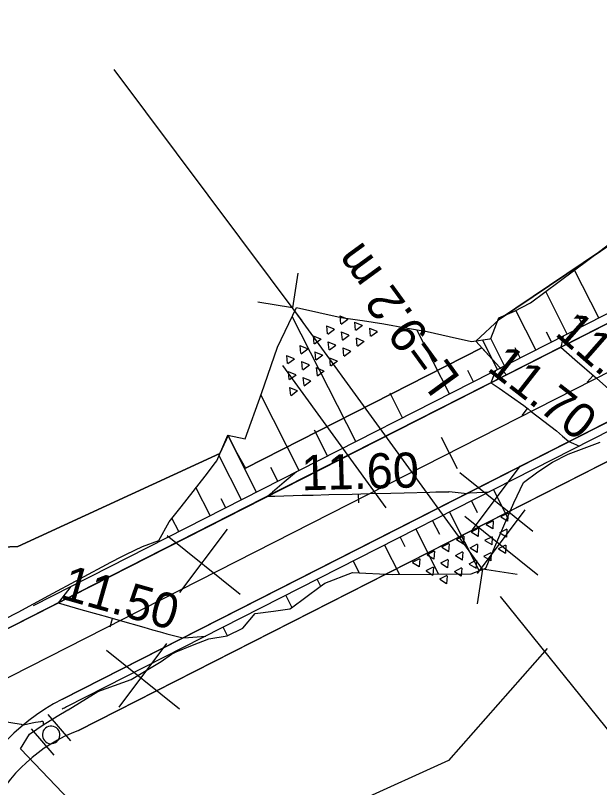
# Model space of a CAD drawing. Extents: x 554247.5 to 554326.1, y 6593477.6 to 6593537.1.
# Drawn here: x 554264.74 to 554281.38, y 6593498.07 to 6593520.04 of the extents above; entities that cross this region are included whole.
import ezdxf

# ---------------------------------------------------------------- set-up
doc = ezdxf.new("R2010")
doc.units = 0
for name, color, linetype in [('ASF', 7, 'Continuous'), ('FILL ASF KT', 7, 'Continuous'), ('FILL ROHELINE', 7, 'Continuous'), ('HATCH SILLUTIS', 7, 'Continuous'), ('KRAAV PUHASTAMINE', 7, 'Continuous'), ('LIIKLUSMÄRK', 7, 'Continuous'), ('LIKV', 7, 'Continuous'), ('NÕLV', 7, 'Continuous'), ('PIIRE TÕKKEPUU', 7, 'Continuous'), ('PK', 7, 'Continuous'), ('TELG', 7, 'Continuous'), ('TRUUP', 7, 'Continuous'), ('TRUUP TXT', 7, 'Continuous'), ('VERT', 7, 'Continuous')]:
    doc.layers.add(name, color=color, linetype=linetype)

msp = doc.modelspace()

# ---------------------------------------------------------------- linework, layer by layer
at = {"layer": 'ASF'}
for points in [[(554264.161, 6593502.412), (554285.444, 6593513.231)], [(554286.577, 6593511.002), (554266.083, 6593500.584)]]:
    msp.add_lwpolyline(points, dxfattribs=at)
msp.add_arc((554268.802, 6593495.236), 6, 116.9456, 201.6745, dxfattribs=at)
at = {"layer": 'FILL ASF KT'}
for p, q in [((554285.444, 6593513.231), (554264.161, 6593502.412)), ((554266.083, 6593500.584), (554286.577, 6593511.002))]:
    msp.add_line(p, q, dxfattribs=at)
msp.add_arc((554268.802, 6593495.236), 6, 116.9456, 201.6745, dxfattribs=at)
at = {"layer": 'FILL ROHELINE'}
for p, q in [((554286.577, 6593511.002), (554266.083, 6593500.584)), ((554266.536, 6593499.693), (554287.03, 6593510.111)), ((554264.161, 6593502.412), (554271.79, 6593506.29))]:
    msp.add_line(p, q, dxfattribs=at)
for points in [[(554277.854, 6593510.768), (554278.526, 6593511.403), (554281.872, 6593513.649), (554285.905, 6593516.209), (554288.219, 6593518.918), (554288.941, 6593519.616), (554289.857, 6593520.042), (554293.053, 6593519.84), (554293.641, 6593519.03), (554290.413, 6593516.439)], [(554290.413, 6593516.439), (554293.641, 6593519.03), (554293.053, 6593519.84), (554289.857, 6593520.042), (554288.941, 6593519.616), (554288.219, 6593518.918), (554285.905, 6593516.209), (554281.872, 6593513.649), (554278.526, 6593511.403), (554277.854, 6593510.768)], [(554285.444, 6593513.231), (554278.724, 6593509.815), (554277.854, 6593510.768)], [(554277.854, 6593510.768), (554278.724, 6593509.815), (554285.444, 6593513.231)], [(554266.083, 6593500.584), (554286.577, 6593511.002)], [(554257.556, 6593501.544), (554257.446, 6593501.567), (554257.204, 6593502.641), (554256.756, 6593504.598), (554264.814, 6593504.931), (554270.559, 6593507.573), (554270.797, 6593508.088), (554271.046, 6593507.591), (554271.293, 6593507.159), (554278.029, 6593510.583), (554278.724, 6593509.815), (554271.79, 6593506.29)], [(554271.79, 6593506.29), (554278.724, 6593509.815), (554278.029, 6593510.583), (554271.293, 6593507.159), (554271.046, 6593507.591), (554270.797, 6593508.088), (554270.559, 6593507.573), (554264.814, 6593504.931), (554256.756, 6593504.598), (554257.204, 6593502.641), (554257.446, 6593501.567), (554257.556, 6593501.544)], [(554287.03, 6593510.111), (554266.536, 6593499.693)], [(554271.79, 6593506.29), (554264.161, 6593502.412)]]:
    msp.add_lwpolyline(points, dxfattribs=at)
for centre, radius, start, end in [((554268.802, 6593495.236), 6, 116.9456, 201.6745), ((554268.802, 6593495.236), 6, 116.9456, 201.6745), ((554268.171, 6593495.373), 4.619, 110.7356, 154.1385), ((554268.171, 6593495.373), 4.619, 110.7356, 154.1385)]:
    msp.add_arc(centre, radius, start, end, dxfattribs=at)
at = {"layer": 'HATCH SILLUTIS'}
for p, q in [((554274.197, 6593511.394), (554273.986, 6593511.481)), ((554274.009, 6593511.262), (554273.987, 6593511.49)), ((554274.016, 6593511.258), (554274.206, 6593511.398)), ((554274.431, 6593511.089), (554274.409, 6593511.317)), ((554274.62, 6593511.221), (554274.409, 6593511.307)), ((554273.63, 6593510.981), (554273.608, 6593511.208)), ((554273.819, 6593511.113), (554273.608, 6593511.199)), ((554273.638, 6593510.976), (554273.827, 6593511.117)), ((554274.439, 6593511.084), (554274.628, 6593511.225)), ((554275.042, 6593511.048), (554274.831, 6593511.134)), ((554274.854, 6593510.916), (554274.832, 6593511.143)), ((554273.44, 6593510.831), (554273.229, 6593510.918)), ((554273.252, 6593510.7), (554273.23, 6593510.927)), ((554273.259, 6593510.695), (554273.448, 6593510.836)), ((554274.241, 6593510.939), (554274.03, 6593511.026)), ((554274.053, 6593510.808), (554274.031, 6593511.035)), ((554274.06, 6593510.803), (554274.25, 6593510.944)), ((554274.475, 6593510.635), (554274.453, 6593510.862)), ((554274.664, 6593510.766), (554274.453, 6593510.853)), ((554274.861, 6593510.911), (554275.051, 6593511.052)), ((554273.062, 6593510.55), (554272.85, 6593510.636)), ((554272.873, 6593510.418), (554272.851, 6593510.646)), ((554273.674, 6593510.526), (554273.652, 6593510.754)), ((554273.863, 6593510.658), (554273.652, 6593510.745)), ((554273.682, 6593510.522), (554273.871, 6593510.662)), ((554274.483, 6593510.63), (554274.672, 6593510.771)), ((554272.881, 6593510.413), (554273.07, 6593510.554)), ((554273.484, 6593510.377), (554273.273, 6593510.463)), ((554273.296, 6593510.245), (554273.274, 6593510.472)), ((554274.285, 6593510.485), (554274.074, 6593510.571)), ((554274.097, 6593510.353), (554274.075, 6593510.58)), ((554274.104, 6593510.348), (554274.294, 6593510.489)), ((554272.683, 6593510.268), (554272.472, 6593510.355)), ((554272.495, 6593510.137), (554272.473, 6593510.364)), ((554272.502, 6593510.132), (554272.691, 6593510.273)), ((554273.106, 6593510.095), (554272.894, 6593510.182)), ((554272.917, 6593509.964), (554272.895, 6593510.191)), ((554273.303, 6593510.24), (554273.492, 6593510.381)), ((554273.907, 6593510.203), (554273.695, 6593510.29)), ((554273.718, 6593510.072), (554273.696, 6593510.299)), ((554273.726, 6593510.067), (554273.915, 6593510.208)), ((554272.925, 6593509.959), (554273.114, 6593510.1)), ((554273.528, 6593509.922), (554273.317, 6593510.009)), ((554273.34, 6593509.79), (554273.318, 6593510.018)), ((554272.727, 6593509.814), (554272.516, 6593509.9)), ((554272.539, 6593509.682), (554272.517, 6593509.909)), ((554272.546, 6593509.677), (554272.735, 6593509.818)), ((554272.961, 6593509.509), (554272.939, 6593509.736)), ((554273.347, 6593509.786), (554273.536, 6593509.926)), ((554273.15, 6593509.641), (554272.938, 6593509.727)), ((554272.969, 6593509.504), (554273.158, 6593509.645)), ((554272.771, 6593509.359), (554272.56, 6593509.446)), ((554272.583, 6593509.228), (554272.561, 6593509.455)), ((554272.59, 6593509.223), (554272.779, 6593509.364)), ((554278.763, 6593505.88), (554278.554, 6593505.772)), ((554278.77, 6593505.874), (554278.755, 6593505.646)), ((554278.344, 6593505.663), (554278.135, 6593505.555)), ((554278.351, 6593505.657), (554278.336, 6593505.43)), ((554278.563, 6593505.775), (554278.757, 6593505.655)), ((554277.925, 6593505.447), (554277.716, 6593505.339)), ((554277.725, 6593505.342), (554277.919, 6593505.222)), ((554277.932, 6593505.441), (554277.917, 6593505.213)), ((554278.144, 6593505.558), (554278.338, 6593505.438)), ((554278.733, 6593505.424), (554278.524, 6593505.316)), ((554278.74, 6593505.418), (554278.725, 6593505.19)), ((554277.506, 6593505.231), (554277.297, 6593505.122)), ((554277.305, 6593505.125), (554277.5, 6593505.006)), ((554277.513, 6593505.225), (554277.498, 6593504.997)), ((554278.314, 6593505.208), (554278.105, 6593505.099)), ((554278.321, 6593505.202), (554278.306, 6593504.974)), ((554278.533, 6593505.319), (554278.727, 6593505.199)), ((554277.087, 6593505.014), (554276.878, 6593504.906)), ((554276.886, 6593504.909), (554277.081, 6593504.789)), ((554277.094, 6593505.008), (554277.079, 6593504.78)), ((554277.895, 6593504.991), (554277.686, 6593504.883)), ((554277.902, 6593504.985), (554277.887, 6593504.757)), ((554278.113, 6593505.102), (554278.308, 6593504.983)), ((554278.703, 6593504.968), (554278.494, 6593504.86)), ((554278.71, 6593504.962), (554278.695, 6593504.735)), ((554276.668, 6593504.798), (554276.458, 6593504.689)), ((554276.467, 6593504.692), (554276.662, 6593504.573)), ((554276.675, 6593504.792), (554276.66, 6593504.564)), ((554277.476, 6593504.775), (554277.266, 6593504.667)), ((554277.483, 6593504.769), (554277.468, 6593504.541)), ((554277.694, 6593504.886), (554277.889, 6593504.766)), ((554278.284, 6593504.752), (554278.074, 6593504.644)), ((554278.291, 6593504.746), (554278.276, 6593504.518)), ((554278.502, 6593504.863), (554278.697, 6593504.743)), ((554276.249, 6593504.581), (554276.039, 6593504.473)), ((554276.048, 6593504.476), (554276.243, 6593504.356)), ((554276.256, 6593504.575), (554276.241, 6593504.347)), ((554277.057, 6593504.558), (554276.847, 6593504.45)), ((554277.064, 6593504.552), (554277.049, 6593504.325)), ((554277.275, 6593504.669), (554277.47, 6593504.55)), ((554277.865, 6593504.535), (554277.655, 6593504.427)), ((554277.872, 6593504.53), (554277.857, 6593504.302)), ((554278.083, 6593504.647), (554278.278, 6593504.527)), ((554276.638, 6593504.342), (554276.428, 6593504.234)), ((554276.645, 6593504.336), (554276.629, 6593504.108)), ((554276.856, 6593504.453), (554277.051, 6593504.333)), ((554277.446, 6593504.319), (554277.236, 6593504.211)), ((554277.453, 6593504.313), (554277.437, 6593504.085)), ((554277.664, 6593504.43), (554277.859, 6593504.31)), ((554276.437, 6593504.237), (554276.632, 6593504.117)), ((554277.027, 6593504.103), (554276.817, 6593503.994)), ((554277.033, 6593504.097), (554277.018, 6593503.869)), ((554277.245, 6593504.214), (554277.44, 6593504.094)), ((554276.826, 6593503.997), (554277.021, 6593503.878))]:
    msp.add_line(p, q, dxfattribs=at)
at = {"layer": 'KRAAV PUHASTAMINE'}
for points in [[(554272.908, 6593511.348), (554267.552, 6593518.507)], [(554289.368, 6593490.108), (554278.553, 6593503.507)], [(554279.884, 6593502.023), (554277.072, 6593498.839), (554274.487, 6593497.666), (554265.394, 6593495.804)]]:
    msp.add_lwpolyline(points, dxfattribs=at)
at = {"layer": 'LIIKLUSMÄRK'}
for points in [[(554266.319, 6593499.394), (554265.678, 6593500.143)], [(554265.844, 6593498.988), (554265.204, 6593499.736)]]:
    msp.add_lwpolyline(points, dxfattribs=at)
for start, end in [(40.559, 220.559), (40.559, 220.559), (220.559, 40.559), (220.559, 40.559)]:
    msp.add_arc((554265.76, 6593499.566), 0.25, start, end, dxfattribs=at)
at = {"layer": 'LIKV'}
for points in [[(554277.756, 6593505.407), (554279.114, 6593507.216)], [(554277.394, 6593507.035), (554279.476, 6593505.361)], [(554277.537, 6593505.792), (554279.619, 6593504.118)], [(554277.899, 6593504.164), (554279.257, 6593505.972)], [(554269.422, 6593503.616), (554270.78, 6593505.425)], [(554269.06, 6593505.244), (554271.142, 6593503.571)], [(554267.699, 6593500.354), (554269.057, 6593502.163)], [(554267.337, 6593501.982), (554269.419, 6593500.309)]]:
    msp.add_lwpolyline(points, dxfattribs=at)
at = {"layer": 'NÕLV'}
for p, q in [((554281.36, 6593511.435), (554280.668, 6593512.796)), ((554280.456, 6593510.975), (554279.843, 6593512.181)), ((554279.564, 6593510.522), (554278.993, 6593511.646)), ((554280.908, 6593511.205), (554280.745, 6593511.526)), ((554274.435, 6593507.915), (554272.625, 6593511.474)), ((554277.104, 6593509.272), (554276.178, 6593511.094)), ((554278.673, 6593510.069), (554278.276, 6593510.85)), ((554280.01, 6593510.749), (554279.867, 6593511.031)), ((554278.471, 6593509.966), (554278.041, 6593510.811)), ((554279.119, 6593510.296), (554278.973, 6593510.583)), ((554277.787, 6593509.619), (554277.625, 6593509.939)), ((554275.769, 6593508.593), (554275.413, 6593509.295)), ((554272.825, 6593507.096), (554271.733, 6593509.243)), ((554273.63, 6593507.506), (554273.258, 6593508.237)), ((554271.611, 6593506.479), (554270.789, 6593508.098)), ((554271.179, 6593506.26), (554270.543, 6593507.512)), ((554272.218, 6593506.788), (554272.018, 6593507.181)), ((554270.288, 6593505.807), (554269.883, 6593506.603)), ((554278.354, 6593506.542), (554278.756, 6593505.751)), ((554270.733, 6593506.033), (554270.606, 6593506.284)), ((554277.729, 6593506.224), (554277.896, 6593505.896)), ((554277.104, 6593505.906), (554277.951, 6593504.239)), ((554269.396, 6593505.354), (554269.201, 6593505.737)), ((554276.624, 6593505.662), (554276.817, 6593505.284)), ((554276.145, 6593505.419), (554276.795, 6593504.14)), ((554275.699, 6593505.192), (554275.834, 6593504.928)), ((554275.254, 6593504.966), (554275.677, 6593504.133)), ((554274.362, 6593504.513), (554274.532, 6593504.177)), ((554273.331, 6593503.988), (554273.428, 6593503.798)), ((554272.439, 6593503.535), (554272.614, 6593503.192)), ((554270.778, 6593502.39), (554270.656, 6593502.629))]:
    msp.add_line(p, q, dxfattribs=at)
for points in [[(554278.276, 6593510.85), (554278.509, 6593511.435), (554278.955, 6593511.626), (554279.415, 6593511.861), (554280.228, 6593512.468), (554281.041, 6593513.075), (554281.854, 6593513.683)], [(554270.789, 6593508.098), (554271.288, 6593507.988), (554271.749, 6593509.287), (554272.202, 6593510.602), (554272.75, 6593511.732), (554274.015, 6593511.449), (554274.547, 6593511.369), (554274.623, 6593511.358), (554275.232, 6593511.262), (554275.85, 6593511.151), (554276.465, 6593511.044), (554277.095, 6593510.907), (554277.728, 6593510.766), (554278.25, 6593510.842), (554278.276, 6593510.85)], [(554264.036, 6593502.658), (554264.817, 6593503.064), (554265.698, 6593503.537), (554266.579, 6593504.011), (554267.46, 6593504.484), (554267.771, 6593504.645), (554267.906, 6593504.709), (554268.358, 6593504.924), (554268.829, 6593505.1), (554269.119, 6593505.634), (554269.462, 6593506.062), (554269.801, 6593506.498), (554270.141, 6593506.933), (554270.442, 6593507.317), (554270.482, 6593507.367), (554270.789, 6593508.098)], [(554273.557, 6593503.889), (554274.342, 6593504.186), (554275.491, 6593504.132), (554276.61, 6593504.138), (554277.723, 6593504.155), (554278.137, 6593504.308), (554278.168, 6593504.382), (554278.425, 6593504.982), (554278.682, 6593505.579), (554278.94, 6593506.175), (554279.21, 6593506.747), (554279.617, 6593507.049), (554280.034, 6593507.333), (554280.482, 6593507.555), (554280.936, 6593507.729), (554281.395, 6593507.898)], [(554266.243, 6593500.278), (554267.091, 6593500.797), (554268.039, 6593501.139), (554268.897, 6593501.657), (554269.186, 6593501.863), (554269.319, 6593501.929), (554269.785, 6593502.117), (554270.254, 6593502.297), (554270.77, 6593502.386), (554271.221, 6593502.603), (554271.571, 6593503.017), (554272.095, 6593503.089), (554272.558, 6593503.153), (554272.606, 6593503.187), (554273.42, 6593503.793), (554273.557, 6593503.889)], [(554267.894, 6593496.025), (554264.889, 6593499.172), (554265.146, 6593499.584), (554265.351, 6593499.732), (554265.536, 6593499.852), (554265.935, 6593500.101), (554266.236, 6593500.283)]]:
    msp.add_lwpolyline(points, dxfattribs=at)
at = {"layer": 'PIIRE TÕKKEPUU'}
for points in [[(554265.258, 6593503.25), (554285.331, 6593513.454)], [(554286.69, 6593510.779), (554266.196, 6593500.361)]]:
    msp.add_lwpolyline(points, dxfattribs=at)
msp.add_arc((554268.802, 6593495.236), 5.75, 116.9456, 118.3007, dxfattribs=at)
at = {"layer": 'PK'}
msp.add_line((554277.327, 6593507.141), (554276.874, 6593508.033), dxfattribs=at)
at = {"layer": 'TELG'}
msp.add_lwpolyline([(554259.272, 6593498.524), (554286.011, 6593512.116)], dxfattribs=at)
at = {"layer": 'TRUUP'}
for p, q in [((554272.347, 6593510.075), (554273.429, 6593508.588)), ((554273.429, 6593508.588), (554275.289, 6593506.033))]:
    msp.add_line(p, q, dxfattribs=at)
for points in [[(554272.789, 6593512.711), (554272.633, 6593511.724), (554271.645, 6593511.88)], [(554278.045, 6593504.284), (554272.633, 6593511.724)], [(554279.032, 6593504.128), (554278.045, 6593504.284), (554277.889, 6593503.296)]]:
    msp.add_lwpolyline(points, dxfattribs=at)
at = {"layer": 'VERT'}
for p, q in [((554281.028, 6593509.609), (554281.193, 6593509.796)), ((554279.172, 6593508.66), (554279.325, 6593508.857)), ((554274.519, 6593506.175), (554274.513, 6593506.425)), ((554267.441, 6593502.641), (554267.51, 6593502.882))]:
    msp.add_line(p, q, dxfattribs=at)
for points in [[(554280.339, 6593510.916), (554280.318, 6593510.813), (554280.274, 6593510.603), (554280.67, 6593510.255), (554281.286, 6593509.715), (554281.902, 6593509.174), (554282.298, 6593508.827), (554282.37, 6593508.795), (554282.59, 6593508.695)], [(554278.411, 6593509.936), (554278.374, 6593509.832), (554278.303, 6593509.635), (554278.291, 6593509.608), (554278.283, 6593509.591), (554278.345, 6593509.553), (554278.518, 6593509.431), (554279.217, 6593508.94), (554279.257, 6593508.91), (554279.265, 6593508.904), (554279.34, 6593508.846), (554279.433, 6593508.773), (554280.146, 6593508.216), (554280.317, 6593508.071), (554280.502, 6593507.914), (554280.633, 6593507.859), (554280.803, 6593507.787)], [(554272.749, 6593507.058), (554272.396, 6593506.758), (554272.059, 6593506.471), (554272.023, 6593506.441), (554271.928, 6593506.36), (554272.113, 6593506.365), (554272.125, 6593506.365), (554272.908, 6593506.385), (554273.22, 6593506.392), (554273.665, 6593506.404), (554274.328, 6593506.42), (554274.829, 6593506.433), (554275.436, 6593506.448), (554275.81, 6593506.457), (554276.544, 6593506.476), (554276.714, 6593506.48), (554277.029, 6593506.488), (554277.082, 6593506.488), (554277.098, 6593506.489), (554277.604, 6593506.441), (554277.677, 6593506.453), (554278.095, 6593506.476), (554278.223, 6593506.483), (554278.236, 6593506.482)], [(554266.323, 6593503.791), (554266.061, 6593503.458), (554265.955, 6593503.324), (554266.608, 6593503.138), (554267.092, 6593503.001), (554267.361, 6593502.924), (554267.724, 6593502.821), (554268.403, 6593502.628), (554268.642, 6593502.56), (554268.863, 6593502.497), (554268.926, 6593502.48), (554269.058, 6593502.443), (554269.512, 6593502.328), (554269.673, 6593502.337), (554270.163, 6593502.378)], [(554264.379, 6593499.953), (554264.904, 6593499.87), (554264.906, 6593499.869), (554264.922, 6593499.865), (554264.975, 6593499.856), (554265.215, 6593499.909), (554265.315, 6593499.927), (554265.466, 6593499.95), (554265.495, 6593499.954), (554265.521, 6593499.956), (554265.531, 6593499.941), (554265.531, 6593499.9), (554265.531, 6593499.89), (554265.531, 6593499.887), (554265.532, 6593499.849)]]:
    msp.add_lwpolyline(points, dxfattribs=at)

# ---------------------------------------------------------------- texts
at = {"layer": 'TRUUP TXT'}
msp.add_text('L=9.2 m', height=1, rotation=126.0332, dxfattribs=at).set_placement((554277.441, 6593509.712))
at = {"layer": 'VERT'}
for s, rotation, p in [('11.80', 318.747, (554280.073, 6593510.963)), ('11.70', 321.9927, (554278.141, 6593509.959)), ('11.60', 1.4325, (554272.898, 6593506.527)), ('11.50', 344.1404, (554265.997, 6593503.455))]:
    msp.add_text(s, height=1, rotation=rotation, dxfattribs=at).set_placement(p)

doc.saveas('drawing.dxf')
